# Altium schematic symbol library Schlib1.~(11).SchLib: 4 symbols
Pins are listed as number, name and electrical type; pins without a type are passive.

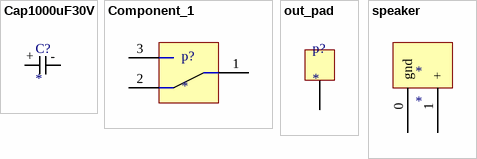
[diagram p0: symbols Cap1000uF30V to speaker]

## Cap1000uF30V
designator C?
Capasitance: 1000uF; Voltage: 30V
footprint Cap_1000uF_35V - duplicate
pins: + 2, - 3

## Component_1
designator p?
pins: 1 in, 2, 3

## out_pad
designator p?
footprint pad
pins: 0

## speaker
designator *
footprint speaker
pins: 0 gnd, 1 +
